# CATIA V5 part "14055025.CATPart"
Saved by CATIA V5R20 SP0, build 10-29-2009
Part number: 14055025
Definition: NONE
Nomenclature: 14055025
Source: Unknown
Description: 14055025
Bounding box of the stored display mesh (mm): x -12.5 to 50, y -41.5 to 31.6, z -31.6 to 31.6
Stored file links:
  C:\Users\Utente\Desktop\IO LAVORO\3D X SITO CF\X SITO\PLASTICA\RF2\14055025.CATPart
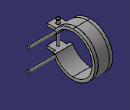
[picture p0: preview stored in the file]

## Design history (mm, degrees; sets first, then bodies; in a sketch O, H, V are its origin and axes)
Body1 "14055025" (main body)
  Solid1: solid without history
